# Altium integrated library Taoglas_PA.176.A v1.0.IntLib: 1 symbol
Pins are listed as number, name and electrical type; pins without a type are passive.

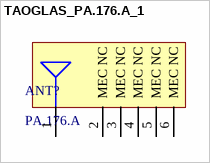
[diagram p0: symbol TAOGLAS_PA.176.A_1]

## TAOGLAS_PA.176.A_1
designator ANT?, comment PA.176.A
ANTENNA SMT 800MHz ~ 2200 MHZ; ComponentLibStatus: Created; MFG: Taoglas; Temp_High: +85C; Temp_Low: -40C
footprint PA.176.A (4G/5G 1.7GHz-6GHz Ceramic Antenna)
pins: 1 RF OUT, 2 MEC NC, 3 MEC NC, 4 MEC NC, 5 MEC NC, 6 MEC NC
